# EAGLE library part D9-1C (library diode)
8 DIODES SIL, common cathode
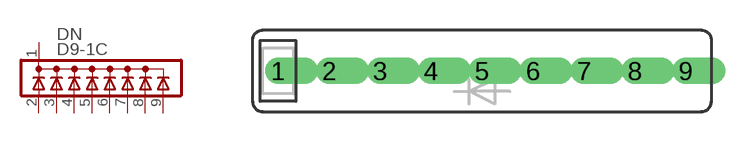
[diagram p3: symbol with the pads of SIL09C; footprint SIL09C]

Designator prefix DN

## D9-1C  [SIL09C]
1  C  pas
2  2  pas
3  3  pas
4  4  pas
5  5  pas
6  6  pas
7  7  pas
8  8  pas
9  9  pas

## Footprint SIL09C (pad centres in mm)
8 DIODES single in line 8 diodes with common cathode
drill 0.813 offset: 1 -10.16,0; 2 -7.62,0; 3 -5.08,0; 4 -2.54,0; 5 0,0; 6 2.54,0; 7 5.08,0; 8 7.62,0; 9 10.16,0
